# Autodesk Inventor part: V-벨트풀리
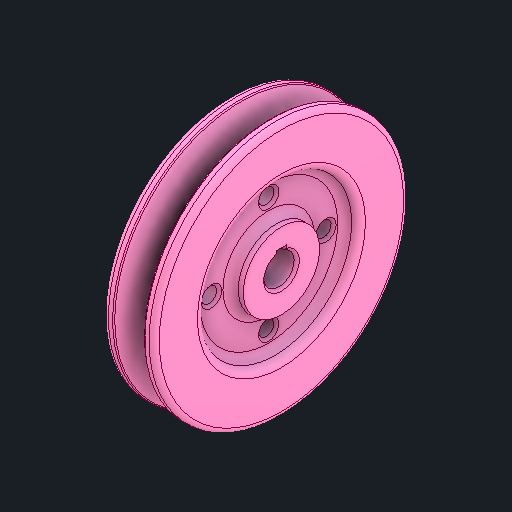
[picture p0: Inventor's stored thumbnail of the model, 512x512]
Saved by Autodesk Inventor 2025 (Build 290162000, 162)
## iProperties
Created: 2025-08
Part Number: V-벨트풀리
Material: 강철, 연강
Document SubType Name: Modeling
Designer: infra023
Density: 7.86 g/cm^3
Appearance: 기본값
Author: jhkim
Sending System: Autodesk Inventor 2026
Preprocessor: ST-DEVELOPER v20.1
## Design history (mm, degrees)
feature "솔리드1"
node "솔리드2"
